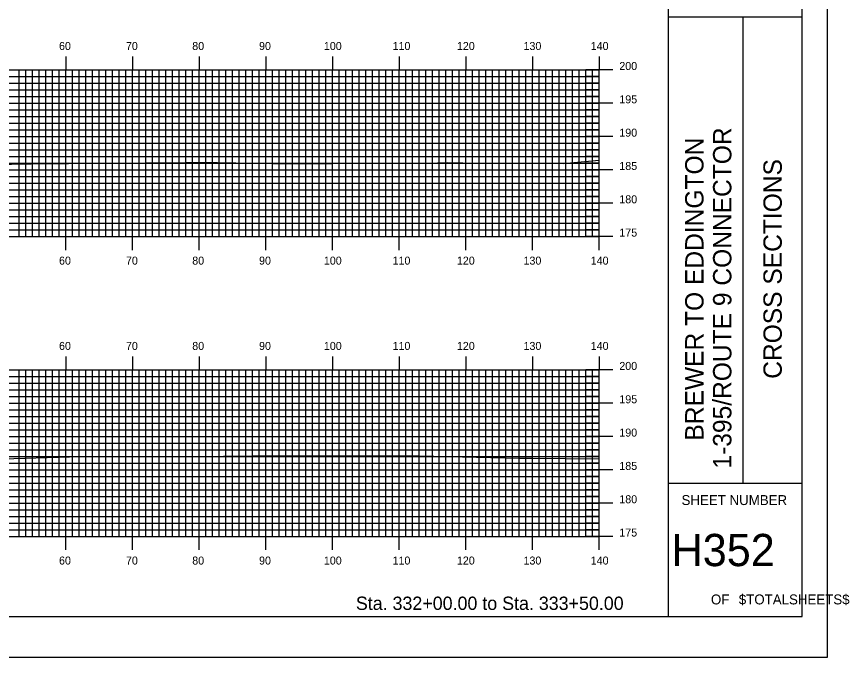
# Model space of a CAD drawing. Extents: x 1822785 to 1823129, y 442591 to 442811.
# Drawn here: x 1823003.9 to 1823128.8, y 442590.5 to 442686.7 of the extents above; entities that cross this region are included whole.
import ezdxf

# ---------------------------------------------------------------- set-up
doc = ezdxf.new("R2010")
doc.units = 0
for name, color, linetype in [('BORDER', 7, 'Continuous'), ('H_V ANNOTATION', 7, 'Continuous'), ('MAJOR', 7, 'Continuous'), ('MINOR', 7, 'Continuous'), ('PLOT BOUNDARY', 7, 'Continuous'), ('S_Roadway_Centerline', 7, 'Continuous')]:
    doc.layers.add(name, color=color, linetype=linetype)

msp = doc.modelspace()

# ---------------------------------------------------------------- linework, layer by layer
at = {"layer": 'BORDER'}
for p, q in [((1823101.68, 442596.67), (1823101.68, 442806.67)), ((1823101.68, 442686.67), (1823121.68, 442686.67)), ((1823112.86, 442616.67), (1823112.86, 442686.67)), ((1823101.68, 442616.67), (1823121.68, 442616.67))]:
    msp.add_line(p, q, dxfattribs=at)
msp.add_lwpolyline([(1822801.68, 442596.67), (1823121.68, 442596.67), (1823121.68, 442806.67), (1822801.68, 442806.67)], close=True, dxfattribs=at)
at = {"layer": 'MAJOR'}
for p, q in [((1823011.28, 442680.67), (1823011.28, 442678.67)), ((1823021.28, 442680.67), (1823021.28, 442678.67)), ((1823031.28, 442680.67), (1823031.28, 442678.67)), ((1823041.28, 442680.67), (1823041.28, 442678.67)), ((1823051.28, 442680.67), (1823051.28, 442678.67)), ((1823061.28, 442680.67), (1823061.28, 442678.67)), ((1823071.28, 442680.67), (1823071.28, 442678.67)), ((1823081.28, 442680.67), (1823081.28, 442678.67)), ((1823091.28, 442680.67), (1823091.28, 442678.67)), ((1822811.28, 442678.67), (1823091.28, 442678.67)), ((1822811.28, 442678.67), (1823091.28, 442678.67)), ((1823011.28, 442653.67), (1823011.28, 442678.67)), ((1823021.28, 442653.67), (1823021.28, 442678.67)), ((1823031.28, 442653.67), (1823031.28, 442678.67)), ((1823041.28, 442653.67), (1823041.28, 442678.67)), ((1823051.28, 442653.67), (1823051.28, 442678.67)), ((1823061.28, 442653.67), (1823061.28, 442678.67)), ((1823071.28, 442653.67), (1823071.28, 442678.67)), ((1823081.28, 442653.67), (1823081.28, 442678.67)), ((1823093.29, 442678.67), (1823089.28, 442678.67)), ((1823091.28, 442653.67), (1823091.28, 442678.67)), ((1823091.28, 442653.67), (1823091.28, 442678.67)), ((1822811.28, 442673.67), (1823091.28, 442673.67)), ((1823093.29, 442673.67), (1823089.28, 442673.67)), ((1822811.28, 442668.67), (1823091.28, 442668.67)), ((1823093.29, 442668.67), (1823089.28, 442668.67)), ((1822811.28, 442663.67), (1823091.28, 442663.67)), ((1823093.29, 442663.67), (1823089.28, 442663.67)), ((1822811.28, 442658.67), (1823091.28, 442658.67)), ((1823093.29, 442658.67), (1823089.28, 442658.67)), ((1822811.28, 442653.67), (1823091.28, 442653.67)), ((1822811.28, 442653.67), (1823091.28, 442653.67)), ((1823011.28, 442651.66), (1823011.28, 442653.67)), ((1823021.28, 442651.66), (1823021.28, 442653.67)), ((1823031.28, 442651.66), (1823031.28, 442653.67)), ((1823041.28, 442651.66), (1823041.28, 442653.67)), ((1823051.28, 442651.66), (1823051.28, 442653.67)), ((1823061.28, 442651.66), (1823061.28, 442653.67)), ((1823071.28, 442651.66), (1823071.28, 442653.67)), ((1823081.28, 442651.66), (1823081.28, 442653.67)), ((1823093.29, 442653.67), (1823089.28, 442653.67)), ((1823091.28, 442651.66), (1823091.28, 442653.67)), ((1823011.28, 442635.67), (1823011.28, 442633.67)), ((1823021.28, 442635.67), (1823021.28, 442633.67)), ((1823031.28, 442635.67), (1823031.28, 442633.67)), ((1823041.28, 442635.67), (1823041.28, 442633.67)), ((1823051.28, 442635.67), (1823051.28, 442633.67)), ((1823061.28, 442635.67), (1823061.28, 442633.67)), ((1823071.28, 442635.67), (1823071.28, 442633.67)), ((1823081.28, 442635.67), (1823081.28, 442633.67)), ((1823091.28, 442635.67), (1823091.28, 442633.67)), ((1822811.28, 442633.67), (1823091.28, 442633.67)), ((1822811.28, 442633.67), (1823091.28, 442633.67)), ((1823011.28, 442608.67), (1823011.28, 442633.67)), ((1823021.28, 442608.67), (1823021.28, 442633.67)), ((1823031.28, 442608.67), (1823031.28, 442633.67)), ((1823041.28, 442608.67), (1823041.28, 442633.67)), ((1823051.28, 442608.67), (1823051.28, 442633.67)), ((1823061.28, 442608.67), (1823061.28, 442633.67)), ((1823071.28, 442608.67), (1823071.28, 442633.67)), ((1823081.28, 442608.67), (1823081.28, 442633.67)), ((1823093.29, 442633.67), (1823089.28, 442633.67)), ((1823091.28, 442608.67), (1823091.28, 442633.67)), ((1823091.28, 442608.67), (1823091.28, 442633.67)), ((1822811.28, 442628.67), (1823091.28, 442628.67)), ((1823093.29, 442628.67), (1823089.28, 442628.67)), ((1822811.28, 442623.67), (1823091.28, 442623.67)), ((1823093.29, 442623.67), (1823089.28, 442623.67)), ((1822811.28, 442618.67), (1823091.28, 442618.67)), ((1823093.29, 442618.67), (1823089.28, 442618.67)), ((1822811.28, 442613.67), (1823091.28, 442613.67)), ((1823093.29, 442613.67), (1823089.28, 442613.67)), ((1822811.28, 442608.67), (1823091.28, 442608.67)), ((1822811.28, 442608.67), (1823091.28, 442608.67)), ((1823011.28, 442606.66), (1823011.28, 442608.67)), ((1823021.28, 442606.66), (1823021.28, 442608.67)), ((1823031.28, 442606.66), (1823031.28, 442608.67)), ((1823041.28, 442606.66), (1823041.28, 442608.67)), ((1823051.28, 442606.66), (1823051.28, 442608.67)), ((1823061.28, 442606.66), (1823061.28, 442608.67)), ((1823071.28, 442606.66), (1823071.28, 442608.67)), ((1823081.28, 442606.66), (1823081.28, 442608.67)), ((1823093.29, 442608.67), (1823089.28, 442608.67)), ((1823091.28, 442606.66), (1823091.28, 442608.67))]:
    msp.add_line(p, q, dxfattribs=at)
at = {"layer": 'MINOR'}
for p, q in [((1822811.28, 442677.67), (1823091.28, 442677.67)), ((1823004.28, 442653.67), (1823004.28, 442678.67)), ((1823005.28, 442653.67), (1823005.28, 442678.67)), ((1823006.28, 442653.67), (1823006.28, 442678.67)), ((1823007.28, 442653.67), (1823007.28, 442678.67)), ((1823008.28, 442653.67), (1823008.28, 442678.67)), ((1823009.28, 442653.67), (1823009.28, 442678.67)), ((1823010.28, 442653.67), (1823010.28, 442678.67)), ((1823012.28, 442653.67), (1823012.28, 442678.67)), ((1823013.28, 442653.67), (1823013.28, 442678.67)), ((1823014.28, 442653.67), (1823014.28, 442678.67)), ((1823015.28, 442653.67), (1823015.28, 442678.67)), ((1823016.28, 442653.67), (1823016.28, 442678.67)), ((1823017.28, 442653.67), (1823017.28, 442678.67)), ((1823018.28, 442653.67), (1823018.28, 442678.67)), ((1823019.28, 442653.67), (1823019.28, 442678.67)), ((1823020.28, 442653.67), (1823020.28, 442678.67)), ((1823022.28, 442653.67), (1823022.28, 442678.67)), ((1823023.28, 442653.67), (1823023.28, 442678.67)), ((1823024.28, 442653.67), (1823024.28, 442678.67)), ((1823025.28, 442653.67), (1823025.28, 442678.67)), ((1823026.28, 442653.67), (1823026.28, 442678.67)), ((1823027.28, 442653.67), (1823027.28, 442678.67)), ((1823028.28, 442653.67), (1823028.28, 442678.67)), ((1823029.28, 442653.67), (1823029.28, 442678.67)), ((1823030.28, 442653.67), (1823030.28, 442678.67)), ((1823032.28, 442653.67), (1823032.28, 442678.67)), ((1823033.28, 442653.67), (1823033.28, 442678.67)), ((1823034.28, 442653.67), (1823034.28, 442678.67)), ((1823035.28, 442653.67), (1823035.28, 442678.67)), ((1823036.28, 442653.67), (1823036.28, 442678.67)), ((1823037.28, 442653.67), (1823037.28, 442678.67)), ((1823038.28, 442653.67), (1823038.28, 442678.67)), ((1823039.28, 442653.67), (1823039.28, 442678.67)), ((1823040.28, 442653.67), (1823040.28, 442678.67)), ((1823042.28, 442653.67), (1823042.28, 442678.67)), ((1823043.28, 442653.67), (1823043.28, 442678.67)), ((1823044.28, 442653.67), (1823044.28, 442678.67)), ((1823045.28, 442653.67), (1823045.28, 442678.67)), ((1823046.28, 442653.67), (1823046.28, 442678.67)), ((1823047.28, 442653.67), (1823047.28, 442678.67)), ((1823048.28, 442653.67), (1823048.28, 442678.67)), ((1823049.28, 442653.67), (1823049.28, 442678.67)), ((1823050.28, 442653.67), (1823050.28, 442678.67)), ((1823052.28, 442653.67), (1823052.28, 442678.67)), ((1823053.28, 442653.67), (1823053.28, 442678.67)), ((1823054.28, 442653.67), (1823054.28, 442678.67)), ((1823055.28, 442653.67), (1823055.28, 442678.67)), ((1823056.28, 442653.67), (1823056.28, 442678.67)), ((1823057.28, 442653.67), (1823057.28, 442678.67)), ((1823058.28, 442653.67), (1823058.28, 442678.67)), ((1823059.28, 442653.67), (1823059.28, 442678.67)), ((1823060.28, 442653.67), (1823060.28, 442678.67)), ((1823062.28, 442653.67), (1823062.28, 442678.67)), ((1823063.28, 442653.67), (1823063.28, 442678.67)), ((1823064.28, 442653.67), (1823064.28, 442678.67)), ((1823065.28, 442653.67), (1823065.28, 442678.67)), ((1823066.28, 442653.67), (1823066.28, 442678.67)), ((1823067.28, 442653.67), (1823067.28, 442678.67)), ((1823068.28, 442653.67), (1823068.28, 442678.67)), ((1823069.28, 442653.67), (1823069.28, 442678.67)), ((1823070.28, 442653.67), (1823070.28, 442678.67)), ((1823072.28, 442653.67), (1823072.28, 442678.67)), ((1823073.28, 442653.67), (1823073.28, 442678.67)), ((1823074.28, 442653.67), (1823074.28, 442678.67)), ((1823075.28, 442653.67), (1823075.28, 442678.67)), ((1823076.28, 442653.67), (1823076.28, 442678.67)), ((1823077.28, 442653.67), (1823077.28, 442678.67)), ((1823078.28, 442653.67), (1823078.28, 442678.67)), ((1823079.28, 442653.67), (1823079.28, 442678.67)), ((1823080.28, 442653.67), (1823080.28, 442678.67)), ((1823082.28, 442653.67), (1823082.28, 442678.67)), ((1823083.28, 442653.67), (1823083.28, 442678.67)), ((1823084.28, 442653.67), (1823084.28, 442678.67)), ((1823085.28, 442653.67), (1823085.28, 442678.67)), ((1823086.28, 442653.67), (1823086.28, 442678.67)), ((1823087.28, 442653.67), (1823087.28, 442678.67)), ((1823088.28, 442653.67), (1823088.28, 442678.67)), ((1823089.28, 442653.67), (1823089.28, 442678.67)), ((1823091.28, 442677.67), (1823089.28, 442677.67)), ((1823090.28, 442653.67), (1823090.28, 442678.67)), ((1822811.28, 442676.67), (1823091.28, 442676.67)), ((1823091.28, 442676.67), (1823089.28, 442676.67)), ((1822811.28, 442675.67), (1823091.28, 442675.67)), ((1823091.28, 442675.67), (1823089.28, 442675.67)), ((1822811.28, 442674.67), (1823091.28, 442674.67)), ((1823091.28, 442674.67), (1823089.28, 442674.67)), ((1822811.28, 442672.67), (1823091.28, 442672.67)), ((1823091.28, 442672.67), (1823089.28, 442672.67)), ((1822811.28, 442671.67), (1823091.28, 442671.67)), ((1823091.28, 442671.67), (1823089.28, 442671.67)), ((1822811.28, 442670.67), (1823091.28, 442670.67)), ((1823091.28, 442670.67), (1823089.28, 442670.67)), ((1822811.28, 442669.67), (1823091.28, 442669.67)), ((1823091.28, 442669.67), (1823089.28, 442669.67)), ((1822811.28, 442667.67), (1823091.28, 442667.67)), ((1823091.28, 442667.67), (1823089.28, 442667.67)), ((1822811.28, 442666.67), (1823091.28, 442666.67)), ((1823091.28, 442666.67), (1823089.28, 442666.67)), ((1822811.28, 442665.67), (1823091.28, 442665.67)), ((1823091.28, 442665.67), (1823089.28, 442665.67)), ((1822811.28, 442664.67), (1823091.28, 442664.67)), ((1823091.28, 442664.67), (1823089.28, 442664.67)), ((1822811.28, 442662.67), (1823091.28, 442662.67)), ((1823091.28, 442662.67), (1823089.28, 442662.67)), ((1822811.28, 442661.67), (1823091.28, 442661.67)), ((1823091.28, 442661.67), (1823089.28, 442661.67)), ((1822811.28, 442660.67), (1823091.28, 442660.67)), ((1823091.28, 442660.67), (1823089.28, 442660.67)), ((1822811.28, 442659.67), (1823091.28, 442659.67)), ((1823091.28, 442659.67), (1823089.28, 442659.67)), ((1822811.28, 442657.67), (1823091.28, 442657.67)), ((1823091.28, 442657.67), (1823089.28, 442657.67)), ((1822811.28, 442656.67), (1823091.28, 442656.67)), ((1823091.28, 442656.67), (1823089.28, 442656.67)), ((1822811.28, 442655.67), (1823091.28, 442655.67)), ((1823091.28, 442655.67), (1823089.28, 442655.67)), ((1822811.28, 442654.67), (1823091.28, 442654.67)), ((1823091.28, 442654.67), (1823089.28, 442654.67)), ((1822811.28, 442632.67), (1823091.28, 442632.67)), ((1823004.28, 442608.67), (1823004.28, 442633.67)), ((1823005.28, 442608.67), (1823005.28, 442633.67)), ((1823006.28, 442608.67), (1823006.28, 442633.67)), ((1823007.28, 442608.67), (1823007.28, 442633.67)), ((1823008.28, 442608.67), (1823008.28, 442633.67)), ((1823009.28, 442608.67), (1823009.28, 442633.67)), ((1823010.28, 442608.67), (1823010.28, 442633.67)), ((1823012.28, 442608.67), (1823012.28, 442633.67)), ((1823013.28, 442608.67), (1823013.28, 442633.67)), ((1823014.28, 442608.67), (1823014.28, 442633.67)), ((1823015.28, 442608.67), (1823015.28, 442633.67)), ((1823016.28, 442608.67), (1823016.28, 442633.67)), ((1823017.28, 442608.67), (1823017.28, 442633.67)), ((1823018.28, 442608.67), (1823018.28, 442633.67)), ((1823019.28, 442608.67), (1823019.28, 442633.67)), ((1823020.28, 442608.67), (1823020.28, 442633.67)), ((1823022.28, 442608.67), (1823022.28, 442633.67)), ((1823023.28, 442608.67), (1823023.28, 442633.67)), ((1823024.28, 442608.67), (1823024.28, 442633.67)), ((1823025.28, 442608.67), (1823025.28, 442633.67)), ((1823026.28, 442608.67), (1823026.28, 442633.67)), ((1823027.28, 442608.67), (1823027.28, 442633.67)), ((1823028.28, 442608.67), (1823028.28, 442633.67)), ((1823029.28, 442608.67), (1823029.28, 442633.67)), ((1823030.28, 442608.67), (1823030.28, 442633.67)), ((1823032.28, 442608.67), (1823032.28, 442633.67)), ((1823033.28, 442608.67), (1823033.28, 442633.67)), ((1823034.28, 442608.67), (1823034.28, 442633.67)), ((1823035.28, 442608.67), (1823035.28, 442633.67)), ((1823036.28, 442608.67), (1823036.28, 442633.67)), ((1823037.28, 442608.67), (1823037.28, 442633.67)), ((1823038.28, 442608.67), (1823038.28, 442633.67)), ((1823039.28, 442608.67), (1823039.28, 442633.67)), ((1823040.28, 442608.67), (1823040.28, 442633.67)), ((1823042.28, 442608.67), (1823042.28, 442633.67)), ((1823043.28, 442608.67), (1823043.28, 442633.67)), ((1823044.28, 442608.67), (1823044.28, 442633.67)), ((1823045.28, 442608.67), (1823045.28, 442633.67)), ((1823046.28, 442608.67), (1823046.28, 442633.67)), ((1823047.28, 442608.67), (1823047.28, 442633.67)), ((1823048.28, 442608.67), (1823048.28, 442633.67)), ((1823049.28, 442608.67), (1823049.28, 442633.67)), ((1823050.28, 442608.67), (1823050.28, 442633.67)), ((1823052.28, 442608.67), (1823052.28, 442633.67)), ((1823053.28, 442608.67), (1823053.28, 442633.67)), ((1823054.28, 442608.67), (1823054.28, 442633.67)), ((1823055.28, 442608.67), (1823055.28, 442633.67)), ((1823056.28, 442608.67), (1823056.28, 442633.67)), ((1823057.28, 442608.67), (1823057.28, 442633.67)), ((1823058.28, 442608.67), (1823058.28, 442633.67)), ((1823059.28, 442608.67), (1823059.28, 442633.67)), ((1823060.28, 442608.67), (1823060.28, 442633.67)), ((1823062.28, 442608.67), (1823062.28, 442633.67)), ((1823063.28, 442608.67), (1823063.28, 442633.67)), ((1823064.28, 442608.67), (1823064.28, 442633.67)), ((1823065.28, 442608.67), (1823065.28, 442633.67)), ((1823066.28, 442608.67), (1823066.28, 442633.67)), ((1823067.28, 442608.67), (1823067.28, 442633.67)), ((1823068.28, 442608.67), (1823068.28, 442633.67)), ((1823069.28, 442608.67), (1823069.28, 442633.67)), ((1823070.28, 442608.67), (1823070.28, 442633.67)), ((1823072.28, 442608.67), (1823072.28, 442633.67)), ((1823073.28, 442608.67), (1823073.28, 442633.67)), ((1823074.28, 442608.67), (1823074.28, 442633.67)), ((1823075.28, 442608.67), (1823075.28, 442633.67)), ((1823076.28, 442608.67), (1823076.28, 442633.67)), ((1823077.28, 442608.67), (1823077.28, 442633.67)), ((1823078.28, 442608.67), (1823078.28, 442633.67)), ((1823079.28, 442608.67), (1823079.28, 442633.67)), ((1823080.28, 442608.67), (1823080.28, 442633.67)), ((1823082.28, 442608.67), (1823082.28, 442633.67)), ((1823083.28, 442608.67), (1823083.28, 442633.67)), ((1823084.28, 442608.67), (1823084.28, 442633.67)), ((1823085.28, 442608.67), (1823085.28, 442633.67)), ((1823086.28, 442608.67), (1823086.28, 442633.67)), ((1823087.28, 442608.67), (1823087.28, 442633.67)), ((1823088.28, 442608.67), (1823088.28, 442633.67)), ((1823089.28, 442608.67), (1823089.28, 442633.67)), ((1823091.28, 442632.67), (1823089.28, 442632.67)), ((1823090.28, 442608.67), (1823090.28, 442633.67)), ((1822811.28, 442631.67), (1823091.28, 442631.67)), ((1823091.28, 442631.67), (1823089.28, 442631.67)), ((1822811.28, 442630.67), (1823091.28, 442630.67)), ((1823091.28, 442630.67), (1823089.28, 442630.67)), ((1822811.28, 442629.67), (1823091.28, 442629.67)), ((1823091.28, 442629.67), (1823089.28, 442629.67)), ((1822811.28, 442627.67), (1823091.28, 442627.67)), ((1823091.28, 442627.67), (1823089.28, 442627.67)), ((1822811.28, 442626.67), (1823091.28, 442626.67)), ((1823091.28, 442626.67), (1823089.28, 442626.67)), ((1822811.28, 442625.67), (1823091.28, 442625.67)), ((1823091.28, 442625.67), (1823089.28, 442625.67)), ((1822811.28, 442624.67), (1823091.28, 442624.67)), ((1823091.28, 442624.67), (1823089.28, 442624.67)), ((1822811.28, 442622.67), (1823091.28, 442622.67)), ((1823091.28, 442622.67), (1823089.28, 442622.67)), ((1822811.28, 442621.67), (1823091.28, 442621.67)), ((1823091.28, 442621.67), (1823089.28, 442621.67)), ((1822811.28, 442620.67), (1823091.28, 442620.67)), ((1823091.28, 442620.67), (1823089.28, 442620.67)), ((1822811.28, 442619.67), (1823091.28, 442619.67)), ((1823091.28, 442619.67), (1823089.28, 442619.67)), ((1822811.28, 442617.67), (1823091.28, 442617.67)), ((1823091.28, 442617.67), (1823089.28, 442617.67)), ((1822811.28, 442616.67), (1823091.28, 442616.67)), ((1823091.28, 442616.67), (1823089.28, 442616.67)), ((1822811.28, 442615.67), (1823091.28, 442615.67)), ((1823091.28, 442615.67), (1823089.28, 442615.67)), ((1822811.28, 442614.67), (1823091.28, 442614.67)), ((1823091.28, 442614.67), (1823089.28, 442614.67)), ((1822811.28, 442612.67), (1823091.28, 442612.67)), ((1823091.28, 442612.67), (1823089.28, 442612.67)), ((1822811.28, 442611.67), (1823091.28, 442611.67)), ((1823091.28, 442611.67), (1823089.28, 442611.67)), ((1822811.28, 442610.67), (1823091.28, 442610.67)), ((1823091.28, 442610.67), (1823089.28, 442610.67)), ((1822811.28, 442609.67), (1823091.28, 442609.67)), ((1823091.28, 442609.67), (1823089.28, 442609.67))]:
    msp.add_line(p, q, dxfattribs=at)
at = {"layer": 'PLOT BOUNDARY'}
msp.add_lwpolyline([(1822785.5, 442590.55), (1823125.5, 442590.55), (1823125.5, 442810.55), (1822785.5, 442810.55)], close=True, dxfattribs=at)
at = {"layer": 'S_Roadway_Centerline'}
for points in [[(1823000.16, 442664.48), (1823006.05, 442664.59), (1823017.33, 442664.71), (1823029.24, 442664.77), (1823034.03, 442664.77), (1823042.29, 442664.65), (1823051.11, 442664.66), (1823067.01, 442664.75), (1823068.03, 442664.75), (1823068.54, 442664.77), (1823070.83, 442664.74), (1823085.84, 442664.64), (1823091.28, 442665.14)], [(1823000.09, 442620.26), (1823013.45, 442620.66), (1823013.51, 442620.66), (1823013.73, 442620.66), (1823030.62, 442620.69), (1823039.24, 442620.78), (1823059.14, 442620.8), (1823064.29, 442620.79), (1823079.3, 442620.45), (1823080.33, 442620.41), (1823080.62, 442620.41), (1823081.19, 442620.41), (1823091.28, 442620.33)]]:
    msp.add_lwpolyline(points, dxfattribs=at)

# ---------------------------------------------------------------- texts
at = {"layer": 'BORDER'}
for s, p in [('1-395/ROUTE 9 CONNECTOR', (1823111.09, 442618.87)), ('BREWER TO EDDINGTON', (1823106.91, 442623.07)), ('CROSS SECTIONS', (1823118.65, 442632.34))]:
    msp.add_text(s, height=2.7557, rotation=90, dxfattribs=at).set_placement(p)
for s, height, p in [('SHEET NUMBER', 1.4905, (1823103.61, 442613.4)), ('H352', 4.839, (1823102.12, 442604.23)), ('$TOTALSHEETS$', 1.4905, (1823112.2, 442598.49)), ('OF', 1.491, (1823108.02, 442598.49))]:
    msp.add_text(s, height=height, dxfattribs=at).set_placement(p)
at = {"layer": 'H_V ANNOTATION'}
for s, height, p in [('60', 1.2, (1823010.25, 442681.67)), ('70', 1.2, (1823020.29, 442681.67)), ('80', 1.2, (1823030.23, 442681.67)), ('90', 1.2, (1823040.25, 442681.67)), ('100', 1.2, (1823049.97, 442681.67)), ('110', 1.2, (1823060.27, 442681.67)), ('120', 1.2, (1823069.92, 442681.67)), ('130', 1.2, (1823079.91, 442681.67)), ('140', 1.2, (1823089.99, 442681.67)), ('200', 1.2, (1823094.28, 442678.67)), ('195', 1.2, (1823094.28, 442673.67)), ('190', 1.2, (1823094.28, 442668.67)), ('185', 1.2, (1823094.28, 442663.67)), ('180', 1.2, (1823094.28, 442658.67)), ('175', 1.2, (1823094.28, 442653.67)), ('60', 1.2, (1823010.25, 442649.47)), ('70', 1.2, (1823020.29, 442649.47)), ('80', 1.2, (1823030.23, 442649.47)), ('90', 1.2, (1823040.25, 442649.47)), ('100', 1.2, (1823049.97, 442649.47)), ('110', 1.2, (1823060.27, 442649.47)), ('120', 1.2, (1823069.92, 442649.47)), ('130', 1.2, (1823079.91, 442649.47)), ('140', 1.2, (1823089.99, 442649.47)), ('60', 1.2, (1823010.25, 442636.67)), ('70', 1.2, (1823020.29, 442636.67)), ('80', 1.2, (1823030.23, 442636.67)), ('90', 1.2, (1823040.25, 442636.67)), ('100', 1.2, (1823049.97, 442636.67)), ('110', 1.2, (1823060.27, 442636.67)), ('120', 1.2, (1823069.92, 442636.67)), ('130', 1.2, (1823079.91, 442636.67)), ('140', 1.2, (1823089.99, 442636.67)), ('200', 1.2, (1823094.28, 442633.67)), ('195', 1.2, (1823094.28, 442628.67)), ('190', 1.2, (1823094.28, 442623.67)), ('185', 1.2, (1823094.28, 442618.67)), ('180', 1.2, (1823094.28, 442613.67)), ('175', 1.2, (1823094.28, 442608.67)), ('60', 1.2, (1823010.25, 442604.47)), ('70', 1.2, (1823020.29, 442604.47)), ('80', 1.2, (1823030.23, 442604.47)), ('90', 1.2, (1823040.25, 442604.47)), ('100', 1.2, (1823049.97, 442604.47)), ('110', 1.2, (1823060.27, 442604.47)), ('120', 1.2, (1823069.92, 442604.47)), ('130', 1.2, (1823079.91, 442604.47)), ('140', 1.2, (1823089.99, 442604.47)), ('Sta. 332+00.00 to Sta. 333+50.00', 2.0004, (1823054.77, 442597.66))]:
    msp.add_text(s, height=height, dxfattribs=at).set_placement(p)

doc.saveas('drawing.dxf')
